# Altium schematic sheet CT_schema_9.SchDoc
size 277 x 170 mm
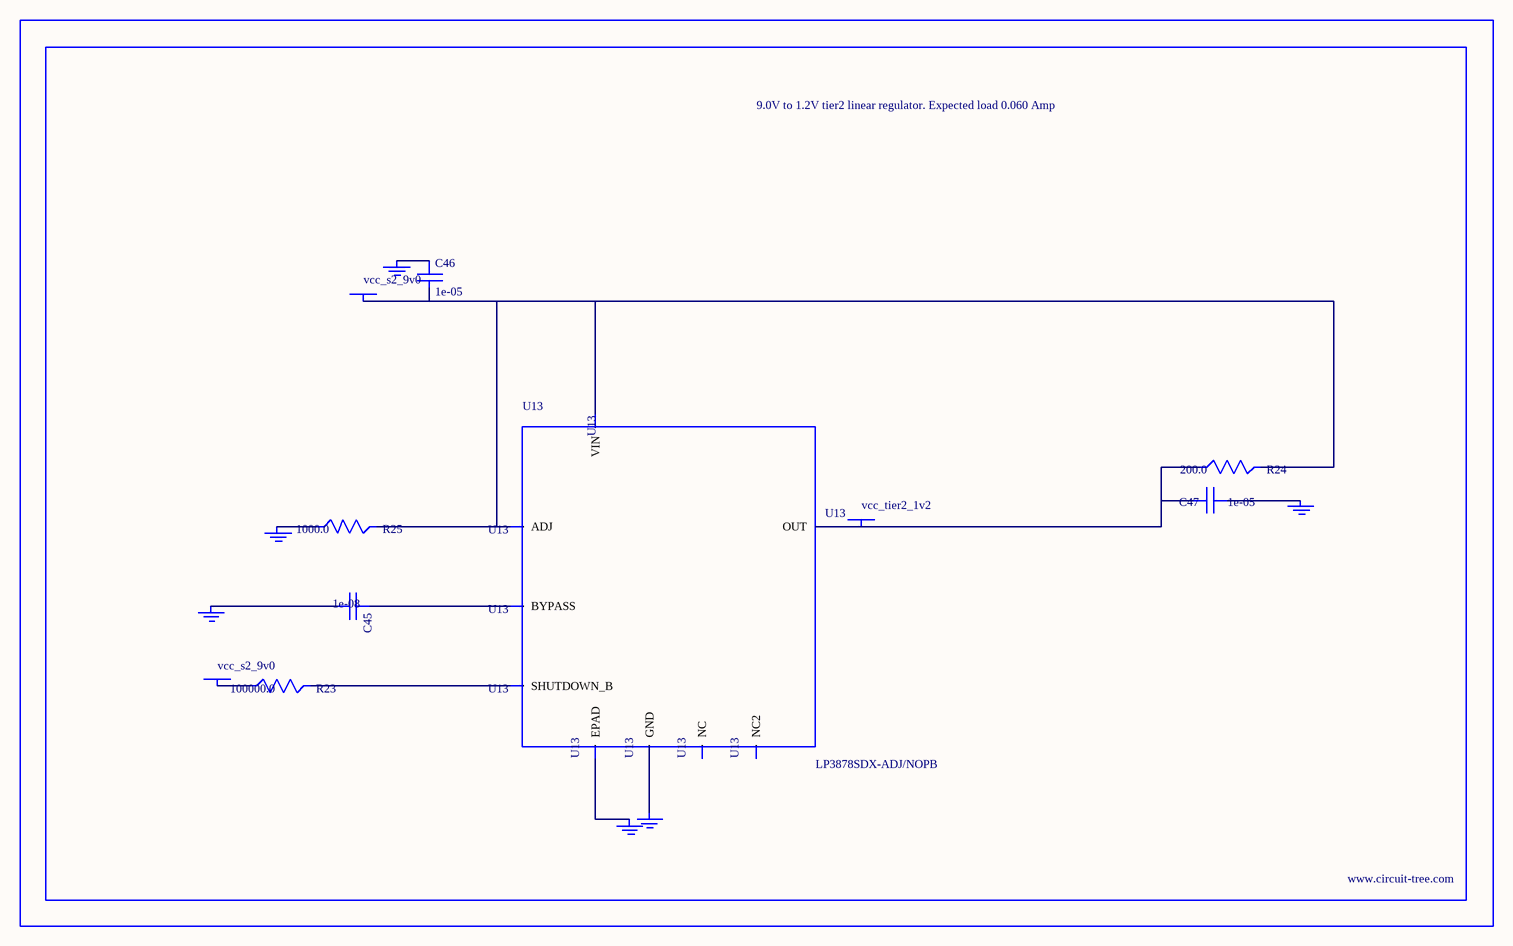
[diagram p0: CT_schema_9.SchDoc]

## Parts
BORDER8  (no value)
C45  1e-08  [C0402]
C46  1e-05  [C1206]
C47  1e-05  [C0805]
GND_INSTANCE_8_0  (no value)
GND_INSTANCE_8_1  (no value)
GND_INSTANCE_8_2  (no value)
GND_INSTANCE_8_3  (no value)
GND_INSTANCE_8_4  (no value)
GND_INSTANCE_8_5  (no value)
POWER_INSTANCE_8_0  vcc_s2_9v0
POWER_INSTANCE_8_1  vcc_s2_9v0
POWER_INSTANCE_8_2  vcc_tier2_1v2
R23  100000.0  [R0603]
R24  200.0  [R0603]
R25  1000.0  [R0603]
U13  LP3878SDX-ADJ/NOPB  [WSON-8]

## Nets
NetC45_1: C45.1 U13.1(BYPASS)
NetC45_2: C45.2 GND_INSTANCE_8_0.0(GND)
NetC46_1: C46.1 GND_INSTANCE_8_1.0(GND)
NetC46_2: C46.2 POWER_INSTANCE_8_0.0(PWR) R24.2 R25.2 U13.4(VIN) U13.6(ADJ)
NetC47_1: C47.1 GND_INSTANCE_8_2.0(GND)
NetC47_2: C47.2 POWER_INSTANCE_8_2.0(PWR) R24.1 U13.5(OUT)
NetGND_INSTANCE_8_3_0: GND_INSTANCE_8_3.0(GND) R25.1
NetGND_INSTANCE_8_4_0: GND_INSTANCE_8_4.0(GND) U13.PAD(EPAD)
NetGND_INSTANCE_8_5_0: GND_INSTANCE_8_5.0(GND) U13.3(GND)
NetPOWER_INSTANCE_8_1_0: POWER_INSTANCE_8_1.0(PWR) R23.1
NetR23_2: R23.2 U13.8(SHUTDOWN_B)

Not connected (* = marked no-connect by the designer): U13 2(NC) 7(NC2)

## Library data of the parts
BORDER8 = BORDER_PAGE8
C45 = C0402C103K3RAC
C46 = C1206C106K3RACTU
C47 = GRM219R60J106ME19D
GND_INSTANCE_8_0-GND_INSTANCE_8_5 = GND
POWER_INSTANCE_8_0-POWER_INSTANCE_8_2 = PWR
R23 = RC0603JR-07100KL
R24 = RC0603JR-07200RL
R25 = RC0603JR-071KL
